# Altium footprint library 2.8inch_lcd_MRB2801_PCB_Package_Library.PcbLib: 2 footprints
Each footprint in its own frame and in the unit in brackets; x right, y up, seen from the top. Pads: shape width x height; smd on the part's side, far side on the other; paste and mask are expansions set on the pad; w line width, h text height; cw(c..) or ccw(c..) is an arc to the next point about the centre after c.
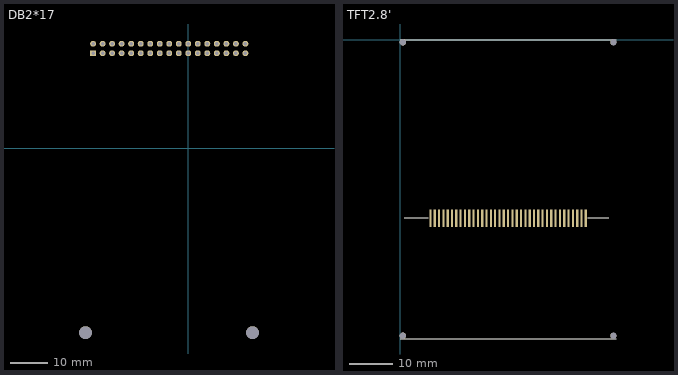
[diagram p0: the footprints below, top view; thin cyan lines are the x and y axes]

## DB2*17 [mil]
pads (36):
  rect 62x62 hole 35: 1(-1000,1000)
  round 62 hole 35: 2(-1000,1100) 3(-900,1000) 4(-900,1100) 5(-800,1000) 6(-800,1100) 7(-700,1000) 8(-700,1100) 9(-600,1000) 10(-600,1100) 11(-500,1000) 12(-500,1100) 13(-400,1000) 14(-400,1100) 15(-300,1000) 16(-300,1100) 17(-200,1000) 18(-200,1100) 19(-100,1000) 20(-100,1100) 21(0,1000) 22(0,1100) 23(100,1000) 24(100,1100) 25(200,1000) 26(200,1100) 27(300,1000) 28(300,1100) 29(400,1000) 30(400,1100) 31(500,1000) 32(500,1100) 33(600,1000) 34(600,1100)
  round 133.86 hole 133.86: ""(-1080,-1935) ""(675,-1935)
Bottom Overlay:
  lines w6: -1050,1050 -950,1050 -950,950 ; -1050,950 -1050,1150 650,1150 650,950 -1050,950

## TFT2.8' [mm]
pads (41):
  rect 0.5x4 smd: 1(7,-41.375) 2(8,-41.375) 3(9,-41.375) 4(10,-41.375) 5(11,-41.375) 6(12,-41.375) 7(13,-41.375) 8(14,-41.375) 9(15,-41.375) 10(16,-41.375) 11(17,-41.375) 12(18,-41.375) 13(19,-41.375) 14(20,-41.375) 15(21,-41.375) 16(22,-41.375) 17(23,-41.375) 18(24,-41.375) 19(25,-41.375) 20(26,-41.375) 21(27,-41.375) 22(28,-41.375) 23(29,-41.375) 24(30,-41.375) 25(31,-41.375) 26(32,-41.375) 27(33,-41.375) 28(34,-41.375) 29(35,-41.375) 30(36,-41.375) 31(37,-41.375) 32(38,-41.375) 33(39,-41.375) 34(40,-41.375) 35(41,-41.375) 36(42,-41.375) 37(43,-41.375)
  round 1.4 hole 1.4: 38(49.375,-0.625) 40(49.375,-68.625)
  round 1.5 hole 1.5: 39(0.625,-0.625) 41(0.625,-68.625)
Top Overlay:
  lines w0.254: 0,-69.3 50,-69.3 ; 0,0 50,0 ; 0.96,-41.275 6.477,-41.275 ; 43.461,-41.275 48.278,-41.275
